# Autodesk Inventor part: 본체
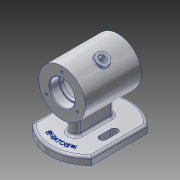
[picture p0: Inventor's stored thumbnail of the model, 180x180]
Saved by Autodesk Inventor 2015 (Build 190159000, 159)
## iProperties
Created: 2022-02
Part Number: 본체
Material: 알루미늄 6061
Document SubType Name: Modeling
Designer: pc-04
Density: 2.7 g/cm^3
Appearance: 알루미늄 - 평지
Mass: 495.287 g
Surface Area: 489.835 cm^2
Volume: 183.44 cm^3
Author: pc-04
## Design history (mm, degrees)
sketch "스케치1"
  geometry: C1 r 30 at (0, 0); 1 further point
  constraints: 1 centre point, 1 coincident
  dimensions: "d0" = 60 diameter of C1
extrude "돌출1" new body sketch "스케치1" distance "d1" = 72; taper "d2" = 0 deg
sketch "스케치2"
  geometry: L1 (72, -30)-(72, 30) reference; L2 (0, 0)-(72, 0); L3 (0, 0)-(12, 0); L4 (12, 0)-(12, 16); L5 (12, 16)-(0, 16); L6 (0, 16)-(0, 0); L7 (12, 0)-(16, 0); L8 (16, 0)-(16, 14); L9 (16, 14)-(12, 14); L10 (12, 14)-(12, 0); L11 (16, 0)-(56, 0); L12 (56, 0)-(56, 25); L13 (56, 25)-(16, 25); L14 (16, 25)-(16, 0); L15 (56, 0)-(60, 0); L16 (60, 0)-(60, 14); L17 (60, 14)-(56, 14); L18 (56, 14)-(56, 0); L19 (60, 0)-(72, 0); L20 (72, 0)-(72, 16); L21 (72, 16)-(60, 16); L22 (60, 16)-(60, 0); L23 (0, 30)-(0, -30) reference
  constraints: 42 end point, 10 parallel, 5 horizontal, 5 perpendicular, 2 point on line, 1 collinear, 1 midpoint
  dimensions: "d3" = 12 distance of L4.end L5.end; "d4" = 4 distance of L8.end L9.end; "d5" = 40 distance of L12.end L13.end; "d6" = 4 distance of L16.end L17.end; "d7" = 12 distance of L20.end L21.end; "d10" = 50 diameter of L13 L2; "d14" = 32 diameter of L5 L11; "d15" = 28 diameter of L9 L11; "d16" = 32 diameter of L21 L2
revolve "회전1" sketch "스케치2" stored, may be unused: angle "d13" = 90 deg
chamfer "모따기1" distance "d17" = 1; stored, may be unused: second distance "d18" = 2, angle "d19" = 45 deg
fillet "모깎기1" dims "d20" = 0.3
fillet "모깎기2" dims "d21" = 3
sketch "스케치3" dims "d22" = 46
  geometry: 5 further points
  constraints: 1 coincident, 1 vertical alignment, 6 other
  dimensions: "d25" = 360 deg dimension on point (0, 0) point (0, 23) (derived)
hole "구멍1" sketch "스케치3" at (0, 23), (-19.919, -11.5), (19.919, -11.5) diameter "d27" = 3.242; stored, may be unused: countersink angle "d31" = 90 deg, drill point angle "d33" = 118 deg; dims "d28" = 8, "d29" = 4, "d30" = 2, "d32" = 10
node "작업 평면1"
node "작업 평면2"
sketch "스케치4"
  geometry: L1 (30, 72)-(-30, 72) reference; L2 (0, 0)-(0, 72); L3 (-38, 0.504)-(-38, 71.496); L4 (38, 0.504)-(38, 71.496); A1 r 52 centre (0, 36) between (38, 71.496) and (-38, 71.496); A2 r 52 centre (0, 36) between (-38, 0.504) and (38, 0.504)
  constraints: 6 end point, 4 point on circle, 2 centre point, 2 midpoint, 2 parallel
  dimensions: "d38" = 52 radius of A2; "d39" = 52 radius of A1; "d40" = 76 diameter of L4 L2; "d41" = 76 distance between parallel lines of L4 L3
extrude "돌출2" join sketch "스케치4" distance "d42" = 10; taper "d43" = 0 deg
sketch "스케치5"
  geometry: L1 (38, 71.496)-(38, 0.504) reference; L2 (38, 36)-(-38, 36); L3 (-38, 0.504)-(-38, 71.496) reference; L4 (0, -16)-(0, 88); L5 (24, 36)-(-24, 36); L6 (-28.5, 28.5)-(-28.5, 43.5); L7 (-19.5, 28.5)-(-19.5, 31.093); L8 (-19.5, 31.093)-(-19.5, 43.5); L9 (19.5, 28.5)-(19.5, 43.5); L10 (28.5, 28.5)-(28.5, 43.5); A1 r 4.5 centre (-24, 28.5) between (-28.5, 28.5) and (-19.5, 28.5); A2 r 4.5 centre (-24, 43.5) between (-19.5, 43.5) and (-28.5, 43.5); A3 r 4.5 centre (24, 43.5) between (28.5, 43.5) and (19.5, 43.5); A4 r 4.5 centre (24, 28.5) between (19.5, 28.5) and (28.5, 28.5); A5 r 52 centre (0, 36) between (-38, 0.504) and (38, 0.504) reference; A6 r 52 centre (0, 36) between (38, 71.496) and (-38, 71.496) reference; 4 further points
  constraints: 16 end point, 10 point on circle, 7 tangent, 5 midpoint, 4 centre point, 3 horizontal alignment, 2 vertical alignment, 1 coincident, 1 horizontal, 1 point on line, 1 vertical
  dimensions: "d44" = 9 diameter of A1; "d45" = 9 diameter of A2; "d46" = 9 diameter of A3; "d47" = 9 diameter of A4; "d48" = 48 distance of A3.centre A2.centre; "d49" = 15 distance of A2.centre A1.centre; "d50" = 9.5 distance between parallel lines of L1 L10; "d51" = 14 distance from line of L5.start L1; "d52" = 7.5 distance from line of L10.end L2; "d53" = 4.90719 distance from line of L7.end L2
extrude "돌출3" cut sketch "스케치5" distance "d54" = 10; taper "d55" = 0 deg
sketch "스케치6"
  geometry: L1 (38, 71.496)-(38, 0.504) reference; L2 (-38, 0.504)-(-38, 71.496) reference; L3 (0, 17)-(0, 55); L4 (0, -16)-(0, 88); L5 (-7, 17)-(-7, 55); L6 (7, 17)-(7, 55); A1 r 52 centre (0, 36) between (-38, 0.504) and (38, 0.504) reference; A2 r 52 centre (0, 36) between (38, 71.496) and (-38, 71.496) reference; A3 r 7 centre (0, 17) between (-7, 17) and (7, 17); A4 r 7 centre (0, 55) between (7, 55) and (-7, 55); 2 further points
  constraints: 8 end point, 6 point on circle, 4 tangent, 2 centre point, 2 midpoint, 1 vertical, 1 vertical alignment
  dimensions: "d56" = 14 diameter of A3; "d57" = 14 diameter of A4; "d58" = 38 distance of L3.end L3.start
extrude "돌출4" join sketch "스케치6" stored distance "d59" = 10; taper "d60" = 0 deg
sketch "스케치7"
  geometry: L1 (0, -16)-(0, 88); C1 r 42.5 at (0, 36); A1 r 52 centre (0, 36) between (-38, 0.504) and (38, 0.504) reference; A2 r 52 centre (0, 36) between (38, 71.496) and (-38, 71.496) reference; 1 further point
  constraints: 2 end point, 2 point on circle, 1 centre point, 1 coincident, 1 other
  dimensions: "d61" = 85 diameter of C1
feature "엠보싱1" sketch "스케치7" dims "d3" = 12, "d4" = 4, "d5" = 40, "d6" = 4, "d7" = 12, "d10" = 50, "d14" = 32, "d15" = 28, "d16" = 32, "d62" = 0.5, "d63" = 0
fillet "모깎기3" dims "d64" = 3
fillet "모깎기4" dims "d65" = 3
fillet "모깎기5" dims "d66" = 3
sketch "스케치8"
  geometry: L1 (0, 0)-(0, 30); L2 (0, 0)-(25.981, 15); A1 r 30 centre (0, 0) between (0, 30) and (25.981, 15) reference; 1 further point
  constraints: 4 end point, 2 point on circle, 1 vertical
  dimensions: "d68" = 60 deg angle of L1 L2
node "작업 평면4"
node "작업 평면5"
sketch "스케치10"
  geometry: 1 further point
node "작업 평면6"
sketch "스케치11"
  geometry: L1 (30, 0)-(-30, 0) reference; L2 (-30, -72)-(30, -72) reference; L3 (0, 0)-(0, -72); C1 r 8 at (0, -36)
  constraints: 2 end point, 2 midpoint, 1 centre point
  dimensions: "d73" = 16 diameter of C1
extrude "돌출5" join sketch "스케치11" stored distance "d74" = 10; taper "d75" = 0 deg
sketch "스케치12"
  geometry: C1 r 8 at (0, 0) reference; C2 r 4 at (0, 0); 1 further point
  constraints: 1 centre point, 1 coincident
  dimensions: "d76" = 8 diameter of C2
extrude "돌출6" cut sketch "스케치12" stored distance "d77" = 10; taper "d78" = 0 deg
fillet "모깎기6" dims "d79" = 1
node "솔리드1"
mirror "대칭1"
other parameters: "d34" = -62, "d35" = 104, "d69" = 90 deg, "d72" = 33
